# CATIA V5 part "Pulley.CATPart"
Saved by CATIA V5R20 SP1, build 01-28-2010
Part number: Pulley
Bounding box of the stored display mesh (mm): x -40.838 to 40.838, y -33 to 33, z -40.838 to 40.838
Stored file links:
  D:\v5_r20\psrt_files_downloaded\c14\c14-catia-v5r20-figr-14-26 & 27\Part & Asm\Pulley.CATPart
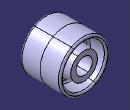
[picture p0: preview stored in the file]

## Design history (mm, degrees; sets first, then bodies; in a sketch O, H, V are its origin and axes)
Body1 (main body)
  Sketch1 on yz-plane, origin (0, 0, 0), H (0, 1, 0), V (0, 0, 1)
    line L1 (0, 13.45) -> (31.5, 13.45)
    point P1 (0, 13.45)
    point P2 (31.5, 13.45)
    line L2 (31.5, 13.45) -> (31.5, 22)
    point P3 (31.5, 22)
    line L3 (31.5, 22) -> (6, 24)
    point P4 (6, 24)
    line L4 (6, 24) -> (6, 33)
    point P5 (6, 33)
    line L5 (6, 33) -> (33, 35)
    point P6 (33, 35)
    line L6 (33, 35) -> (33, 41)
    point P7 (33, 41)
    line L7 (33, 41) -> (0, 41)
    point P8 (0, 41)
    point P9 (0, 41)
    point P10 (-33, 41)
    line L8 (-33, 41) -> (0, 41)
    point P11 (-33, 35)
    line L9 (-33, 35) -> (-33, 41)
    point P12 (-6, 33)
    line L10 (-6, 33) -> (-33, 35)
    point P13 (-6, 24)
    line L11 (-6, 24) -> (-6, 33)
    point P14 (-31.5, 22)
    line L12 (-31.5, 22) -> (-6, 24)
    point P15 (-31.5, 13.45)
    line L13 (-31.5, 13.45) -> (-31.5, 22)
    point P16 (0, 13.45)
    line L14 (0, 13.45) -> (-31.5, 13.45)
    length L1 = 31.5
    distance L1 H = 13.45
    distance P4 H = 24
    distance P3 H = 22
    distance L4 V = 6
    distance P5 H = 33
    distance P6 H = 35
    distance V L6 = 33
    distance L7 H = 41
    coincidence: P1 V, P8 V, P1 P16, P8 P9
    horizontal: L1 H, L7 H
    vertical: L2 V, L4 V, L6 V
    symmetry: P8 P9 V, P7 P10 V, L7 L8 V, P6 P11 V, L6 L9 V, P5 P12 V, L5 L10 V, P4 P13 V, L4 L11 V, P3 P14 V, L3 L12 V, P2 P15 V, L2 L13 V, P1 P16 V, L1 L14 V
  Shaft1: profile Sketch1, axis Sketch1.H, angle 360
  Fillet1: radius 3, on 4 faces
